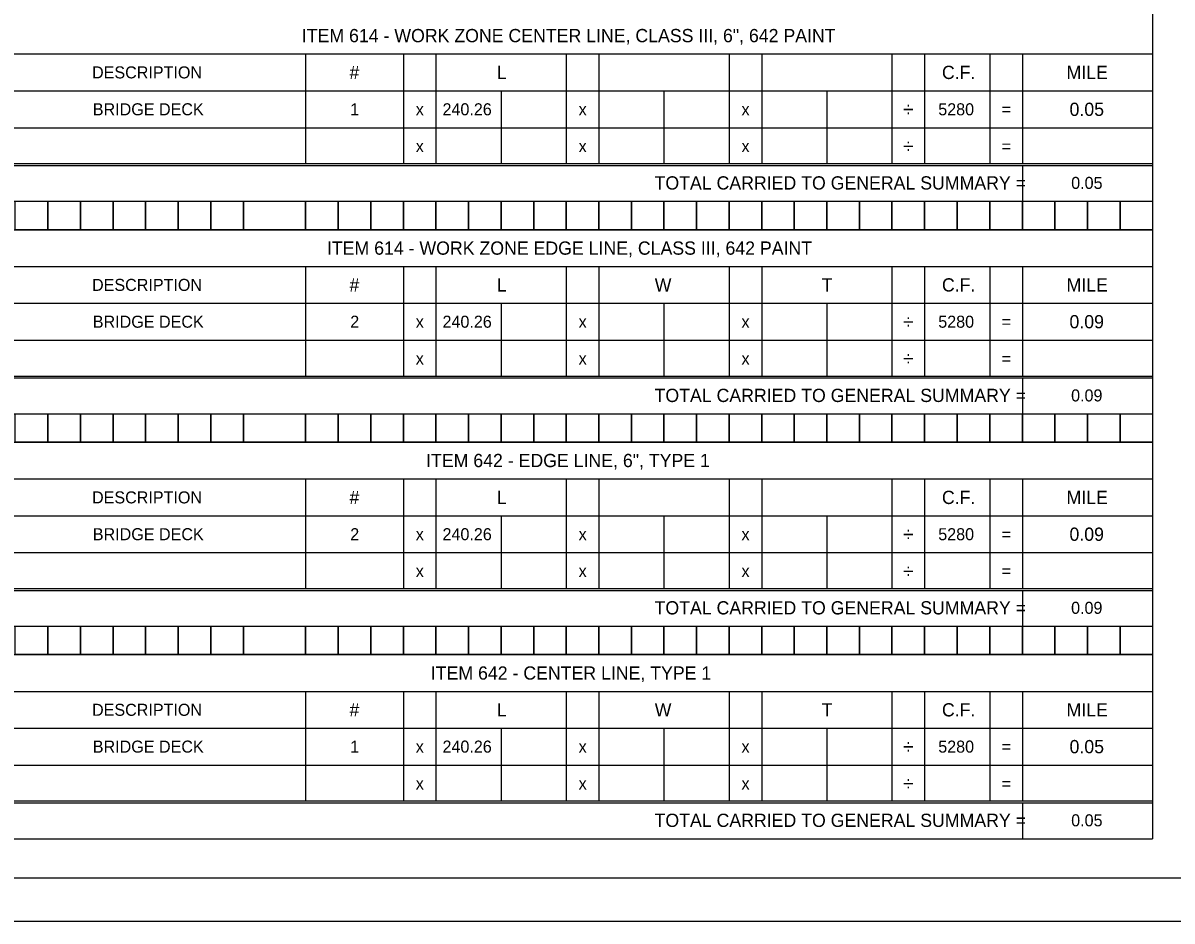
# Model space of a CAD drawing. Extents: x 0 to 34, y 0 to 22.
# Drawn here: x 11.43 to 24.79, y 0 to 10.44 of the extents above; entities that cross this region are included whole.
import ezdxf

# ---------------------------------------------------------------- set-up
doc = ezdxf.new("R2010")
doc.units = 0
for name, color, linetype in [('Default', 7, 'Continuous'), ('SH_Border', 7, 'Continuous'), ('SH_Cut_Line', 7, 'Continuous')]:
    doc.layers.add(name, color=color, linetype=linetype)

msp = doc.modelspace()

# ---------------------------------------------------------------- linework, layer by layer
at = {"layer": 'Default'}
for p, q in [((24.564, 11.279), (24.564, 8.786)), ((10.959, 10.082), (24.564, 10.082)), ((14.714, 10.082), (14.714, 8.808)), ((15.851, 10.082), (15.851, 8.808)), ((16.23, 10.082), (16.23, 8.808)), ((17.745, 10.082), (17.745, 8.808)), ((18.124, 10.082), (18.124, 8.808)), ((19.639, 10.082), (19.639, 8.808)), ((20.018, 10.082), (20.018, 8.808)), ((21.533, 10.082), (21.533, 8.808)), ((21.912, 10.082), (21.912, 8.808)), ((22.67, 10.082), (22.67, 8.808)), ((23.049, 10.082), (23.049, 8.808)), ((10.959, 9.654), (24.564, 9.654)), ((16.987, 9.654), (16.987, 8.808)), ((18.881, 9.654), (18.881, 8.808)), ((20.776, 9.654), (20.776, 8.808)), ((10.959, 9.225), (24.564, 9.225)), ((10.959, 8.808), (24.564, 8.808)), ((10.959, 8.786), (24.564, 8.786)), ((23.049, 8.786), (23.049, 8.369)), ((24.564, 8.808), (24.564, 6.315)), ((10.959, 8.369), (24.564, 8.369)), ((10.959, 8.039), (24.564, 8.039)), ((10.959, 7.611), (24.564, 7.611)), ((14.714, 7.611), (14.714, 6.337)), ((15.851, 7.611), (15.851, 6.337)), ((16.23, 7.611), (16.23, 6.337)), ((17.745, 7.611), (17.745, 6.337)), ((18.124, 7.611), (18.124, 6.337)), ((19.639, 7.611), (19.639, 6.337)), ((20.018, 7.611), (20.018, 6.337)), ((21.533, 7.611), (21.533, 6.337)), ((21.912, 7.611), (21.912, 6.337)), ((22.67, 7.611), (22.67, 6.337)), ((23.049, 7.611), (23.049, 6.337)), ((10.959, 7.183), (24.564, 7.183)), ((16.987, 7.183), (16.987, 6.337)), ((18.881, 7.183), (18.881, 6.337)), ((20.776, 7.183), (20.776, 6.337)), ((10.959, 6.755), (24.564, 6.755)), ((10.959, 6.337), (24.564, 6.337)), ((10.959, 6.315), (24.564, 6.315)), ((23.049, 6.315), (23.049, 5.898)), ((24.564, 6.337), (24.564, 3.845)), ((10.959, 5.898), (24.564, 5.898)), ((10.959, 5.569), (24.564, 5.569)), ((10.959, 5.141), (24.564, 5.141)), ((14.714, 5.141), (14.714, 3.867)), ((15.851, 5.141), (15.851, 3.867)), ((16.23, 5.141), (16.23, 3.867)), ((17.745, 5.141), (17.745, 3.867)), ((18.124, 5.141), (18.124, 3.867)), ((19.639, 5.141), (19.639, 3.867)), ((20.018, 5.141), (20.018, 3.867)), ((21.533, 5.141), (21.533, 3.867)), ((21.912, 5.141), (21.912, 3.867)), ((22.67, 5.141), (22.67, 3.867)), ((23.049, 5.141), (23.049, 3.867)), ((10.959, 4.712), (24.564, 4.712)), ((16.987, 4.712), (16.987, 3.867)), ((18.881, 4.712), (18.881, 3.867)), ((20.776, 4.712), (20.776, 3.867)), ((10.959, 4.284), (24.564, 4.284)), ((10.959, 3.867), (24.564, 3.867)), ((10.959, 3.845), (24.564, 3.845)), ((23.049, 3.845), (23.049, 3.428)), ((24.564, 3.867), (24.564, 1.374)), ((10.959, 3.428), (24.564, 3.428)), ((10.959, 3.098), (24.564, 3.098)), ((10.959, 2.67), (24.564, 2.67)), ((14.714, 2.67), (14.714, 1.396)), ((15.851, 2.67), (15.851, 1.396)), ((16.23, 2.67), (16.23, 1.396)), ((17.745, 2.67), (17.745, 1.396)), ((18.124, 2.67), (18.124, 1.396)), ((19.639, 2.67), (19.639, 1.396)), ((20.018, 2.67), (20.018, 1.396)), ((21.533, 2.67), (21.533, 1.396)), ((21.912, 2.67), (21.912, 1.396)), ((22.67, 2.67), (22.67, 1.396)), ((23.049, 2.67), (23.049, 1.396)), ((10.959, 2.242), (24.564, 2.242)), ((16.987, 2.242), (16.987, 1.396)), ((18.881, 2.242), (18.881, 1.396)), ((20.776, 2.242), (20.776, 1.396)), ((10.959, 1.814), (24.564, 1.814)), ((10.959, 1.396), (24.564, 1.396)), ((10.959, 1.374), (24.564, 1.374)), ((23.049, 1.374), (23.049, 0.957)), ((24.564, 1.396), (24.564, 0.957)), ((10.959, 0.957), (24.564, 0.957))]:
    msp.add_line(p, q, dxfattribs=at)
for points in [[(11.338, 8.369), (11.717, 8.369), (11.717, 8.039), (11.338, 8.039)], [(11.717, 8.369), (12.096, 8.369), (12.096, 8.039), (11.717, 8.039)], [(12.096, 8.369), (12.474, 8.369), (12.474, 8.039), (12.096, 8.039)], [(12.474, 8.369), (12.853, 8.369), (12.853, 8.039), (12.474, 8.039)], [(12.853, 8.369), (13.232, 8.369), (13.232, 8.039), (12.853, 8.039)], [(13.232, 8.369), (13.611, 8.369), (13.611, 8.039), (13.232, 8.039)], [(13.611, 8.369), (13.99, 8.369), (13.99, 8.039), (13.611, 8.039)], [(13.99, 8.369), (14.714, 8.369), (14.714, 8.039), (13.99, 8.039)], [(14.714, 8.369), (15.093, 8.369), (15.093, 8.039), (14.714, 8.039)], [(15.093, 8.369), (15.472, 8.369), (15.472, 8.039), (15.093, 8.039)], [(15.472, 8.369), (15.851, 8.369), (15.851, 8.039), (15.472, 8.039)], [(15.851, 8.369), (16.23, 8.369), (16.23, 8.039), (15.851, 8.039)], [(16.23, 8.369), (16.609, 8.369), (16.609, 8.039), (16.23, 8.039)], [(16.609, 8.369), (16.987, 8.369), (16.987, 8.039), (16.609, 8.039)], [(16.987, 8.369), (17.366, 8.369), (17.366, 8.039), (16.987, 8.039)], [(17.366, 8.369), (17.745, 8.369), (17.745, 8.039), (17.366, 8.039)], [(17.745, 8.369), (18.124, 8.369), (18.124, 8.039), (17.745, 8.039)], [(18.124, 8.369), (18.503, 8.369), (18.503, 8.039), (18.124, 8.039)], [(18.503, 8.369), (18.881, 8.369), (18.881, 8.039), (18.503, 8.039)], [(18.881, 8.369), (19.26, 8.369), (19.26, 8.039), (18.881, 8.039)], [(19.26, 8.369), (19.639, 8.369), (19.639, 8.039), (19.26, 8.039)], [(19.639, 8.369), (20.018, 8.369), (20.018, 8.039), (19.639, 8.039)], [(20.018, 8.369), (20.397, 8.369), (20.397, 8.039), (20.018, 8.039)], [(20.397, 8.369), (20.776, 8.369), (20.776, 8.039), (20.397, 8.039)], [(20.776, 8.369), (21.154, 8.369), (21.154, 8.039), (20.776, 8.039)], [(21.154, 8.369), (21.533, 8.369), (21.533, 8.039), (21.154, 8.039)], [(21.533, 8.369), (21.912, 8.369), (21.912, 8.039), (21.533, 8.039)], [(21.912, 8.369), (22.291, 8.369), (22.291, 8.039), (21.912, 8.039)], [(22.291, 8.369), (22.67, 8.369), (22.67, 8.039), (22.291, 8.039)], [(22.67, 8.369), (23.049, 8.369), (23.049, 8.039), (22.67, 8.039)], [(23.049, 8.369), (23.427, 8.369), (23.427, 8.039), (23.049, 8.039)], [(23.427, 8.369), (23.806, 8.369), (23.806, 8.039), (23.427, 8.039)], [(23.806, 8.369), (24.185, 8.369), (24.185, 8.039), (23.806, 8.039)], [(24.185, 8.369), (24.564, 8.369), (24.564, 8.039), (24.185, 8.039)], [(11.338, 5.898), (11.717, 5.898), (11.717, 5.569), (11.338, 5.569)], [(11.717, 5.898), (12.096, 5.898), (12.096, 5.569), (11.717, 5.569)], [(12.096, 5.898), (12.474, 5.898), (12.474, 5.569), (12.096, 5.569)], [(12.474, 5.898), (12.853, 5.898), (12.853, 5.569), (12.474, 5.569)], [(12.853, 5.898), (13.232, 5.898), (13.232, 5.569), (12.853, 5.569)], [(13.232, 5.898), (13.611, 5.898), (13.611, 5.569), (13.232, 5.569)], [(13.611, 5.898), (13.99, 5.898), (13.99, 5.569), (13.611, 5.569)], [(13.99, 5.898), (14.714, 5.898), (14.714, 5.569), (13.99, 5.569)], [(14.714, 5.898), (15.093, 5.898), (15.093, 5.569), (14.714, 5.569)], [(15.093, 5.898), (15.472, 5.898), (15.472, 5.569), (15.093, 5.569)], [(15.472, 5.898), (15.851, 5.898), (15.851, 5.569), (15.472, 5.569)], [(15.851, 5.898), (16.23, 5.898), (16.23, 5.569), (15.851, 5.569)], [(16.23, 5.898), (16.609, 5.898), (16.609, 5.569), (16.23, 5.569)], [(16.609, 5.898), (16.987, 5.898), (16.987, 5.569), (16.609, 5.569)], [(16.987, 5.898), (17.366, 5.898), (17.366, 5.569), (16.987, 5.569)], [(17.366, 5.898), (17.745, 5.898), (17.745, 5.569), (17.366, 5.569)], [(17.745, 5.898), (18.124, 5.898), (18.124, 5.569), (17.745, 5.569)], [(18.124, 5.898), (18.503, 5.898), (18.503, 5.569), (18.124, 5.569)], [(18.503, 5.898), (18.881, 5.898), (18.881, 5.569), (18.503, 5.569)], [(18.881, 5.898), (19.26, 5.898), (19.26, 5.569), (18.881, 5.569)], [(19.26, 5.898), (19.639, 5.898), (19.639, 5.569), (19.26, 5.569)], [(19.639, 5.898), (20.018, 5.898), (20.018, 5.569), (19.639, 5.569)], [(20.018, 5.898), (20.397, 5.898), (20.397, 5.569), (20.018, 5.569)], [(20.397, 5.898), (20.776, 5.898), (20.776, 5.569), (20.397, 5.569)], [(20.776, 5.898), (21.154, 5.898), (21.154, 5.569), (20.776, 5.569)], [(21.154, 5.898), (21.533, 5.898), (21.533, 5.569), (21.154, 5.569)], [(21.533, 5.898), (21.912, 5.898), (21.912, 5.569), (21.533, 5.569)], [(21.912, 5.898), (22.291, 5.898), (22.291, 5.569), (21.912, 5.569)], [(22.291, 5.898), (22.67, 5.898), (22.67, 5.569), (22.291, 5.569)], [(22.67, 5.898), (23.049, 5.898), (23.049, 5.569), (22.67, 5.569)], [(23.049, 5.898), (23.427, 5.898), (23.427, 5.569), (23.049, 5.569)], [(23.427, 5.898), (23.806, 5.898), (23.806, 5.569), (23.427, 5.569)], [(23.806, 5.898), (24.185, 5.898), (24.185, 5.569), (23.806, 5.569)], [(24.185, 5.898), (24.564, 5.898), (24.564, 5.569), (24.185, 5.569)], [(11.338, 3.428), (11.717, 3.428), (11.717, 3.098), (11.338, 3.098)], [(11.717, 3.428), (12.096, 3.428), (12.096, 3.098), (11.717, 3.098)], [(12.096, 3.428), (12.474, 3.428), (12.474, 3.098), (12.096, 3.098)], [(12.474, 3.428), (12.853, 3.428), (12.853, 3.098), (12.474, 3.098)], [(12.853, 3.428), (13.232, 3.428), (13.232, 3.098), (12.853, 3.098)], [(13.232, 3.428), (13.611, 3.428), (13.611, 3.098), (13.232, 3.098)], [(13.611, 3.428), (13.99, 3.428), (13.99, 3.098), (13.611, 3.098)], [(13.99, 3.428), (14.714, 3.428), (14.714, 3.098), (13.99, 3.098)], [(14.714, 3.428), (15.093, 3.428), (15.093, 3.098), (14.714, 3.098)], [(15.093, 3.428), (15.472, 3.428), (15.472, 3.098), (15.093, 3.098)], [(15.472, 3.428), (15.851, 3.428), (15.851, 3.098), (15.472, 3.098)], [(15.851, 3.428), (16.23, 3.428), (16.23, 3.098), (15.851, 3.098)], [(16.23, 3.428), (16.609, 3.428), (16.609, 3.098), (16.23, 3.098)], [(16.609, 3.428), (16.987, 3.428), (16.987, 3.098), (16.609, 3.098)], [(16.987, 3.428), (17.366, 3.428), (17.366, 3.098), (16.987, 3.098)], [(17.366, 3.428), (17.745, 3.428), (17.745, 3.098), (17.366, 3.098)], [(17.745, 3.428), (18.124, 3.428), (18.124, 3.098), (17.745, 3.098)], [(18.124, 3.428), (18.503, 3.428), (18.503, 3.098), (18.124, 3.098)], [(18.503, 3.428), (18.881, 3.428), (18.881, 3.098), (18.503, 3.098)], [(18.881, 3.428), (19.26, 3.428), (19.26, 3.098), (18.881, 3.098)], [(19.26, 3.428), (19.639, 3.428), (19.639, 3.098), (19.26, 3.098)], [(19.639, 3.428), (20.018, 3.428), (20.018, 3.098), (19.639, 3.098)], [(20.018, 3.428), (20.397, 3.428), (20.397, 3.098), (20.018, 3.098)], [(20.397, 3.428), (20.776, 3.428), (20.776, 3.098), (20.397, 3.098)], [(20.776, 3.428), (21.154, 3.428), (21.154, 3.098), (20.776, 3.098)], [(21.154, 3.428), (21.533, 3.428), (21.533, 3.098), (21.154, 3.098)], [(21.533, 3.428), (21.912, 3.428), (21.912, 3.098), (21.533, 3.098)], [(21.912, 3.428), (22.291, 3.428), (22.291, 3.098), (21.912, 3.098)], [(22.291, 3.428), (22.67, 3.428), (22.67, 3.098), (22.291, 3.098)], [(22.67, 3.428), (23.049, 3.428), (23.049, 3.098), (22.67, 3.098)], [(23.049, 3.428), (23.427, 3.428), (23.427, 3.098), (23.049, 3.098)], [(23.427, 3.428), (23.806, 3.428), (23.806, 3.098), (23.427, 3.098)], [(23.806, 3.428), (24.185, 3.428), (24.185, 3.098), (23.806, 3.098)], [(24.185, 3.428), (24.564, 3.428), (24.564, 3.098), (24.185, 3.098)]]:
    msp.add_lwpolyline(points, close=True, dxfattribs=at)
at = {"layer": 'SH_Border'}
msp.add_lwpolyline([(1.5, 21.5), (33.5, 21.5), (33.5, 0.5), (1.5, 0.5)], close=True, dxfattribs=at)
at = {"layer": 'SH_Cut_Line'}
msp.add_lwpolyline([(0, 0), (34, 0), (34, 22), (0, 22)], close=True, dxfattribs=at)

# ---------------------------------------------------------------- texts
at = {"layer": 'Default'}
for s, height, p in [('ITEM 614 - WORK ZONE CENTER LINE, CLASS III, 6", 642 PAINT', 0.154, (14.67, 10.219)), ('DESCRIPTION', 0.14, (12.23, 9.798)), ('#', 0.154, (15.224, 9.791)), ('L', 0.154, (16.937, 9.791)), ('C.F.', 0.154, (22.114, 9.791)), ('MILE', 0.154, (23.563, 9.791)), ('BRIDGE DECK', 0.14, (12.239, 9.369)), ('1', 0.14, (15.233, 9.369)), ('240.26', 0.14, (16.306, 9.369)), ('÷', 0.168, (21.661, 9.355)), ('5280', 0.14, (22.071, 9.369)), ('0.05', 0.154, (23.598, 9.362)), ('x', 0.14, (15.995, 9.369)), ('x', 0.14, (17.889, 9.369)), ('x', 0.14, (19.783, 9.369)), ('=', 0.14, (22.809, 9.369)), ('x', 0.14, (15.995, 8.941)), ('x', 0.14, (17.889, 8.941)), ('x', 0.14, (19.783, 8.941)), ('÷', 0.168, (21.661, 8.927)), ('=', 0.14, (22.809, 8.941)), ('TOTAL CARRIED TO GENERAL SUMMARY =', 0.154, (18.772, 8.506)), ('0.05', 0.14, (23.617, 8.513)), ('ITEM 614 - WORK ZONE EDGE LINE, CLASS III, 642 PAINT', 0.154, (14.962, 7.748)), ('DESCRIPTION', 0.14, (12.23, 7.327)), ('#', 0.154, (15.224, 7.32)), ('L', 0.154, (16.937, 7.32)), ('W', 0.154, (18.774, 7.32)), ('T', 0.154, (20.716, 7.32)), ('C.F.', 0.154, (22.114, 7.32)), ('MILE', 0.154, (23.563, 7.32)), ('BRIDGE DECK', 0.14, (12.239, 6.899)), ('2', 0.14, (15.233, 6.899)), ('x', 0.14, (15.995, 6.899)), ('240.26', 0.14, (16.306, 6.899)), ('x', 0.14, (17.889, 6.899)), ('x', 0.14, (19.783, 6.899)), ('÷', 0.168, (21.661, 6.885)), ('5280', 0.14, (22.071, 6.899)), ('=', 0.14, (22.809, 6.899)), ('0.09', 0.154, (23.597, 6.892)), ('x', 0.14, (15.995, 6.471)), ('x', 0.14, (17.889, 6.471)), ('x', 0.14, (19.783, 6.471)), ('÷', 0.168, (21.661, 6.457)), ('=', 0.14, (22.809, 6.471)), ('TOTAL CARRIED TO GENERAL SUMMARY =', 0.154, (18.772, 6.035)), ('0.09', 0.14, (23.616, 6.042)), ('ITEM 642 - EDGE LINE, 6", TYPE 1', 0.154, (16.115, 5.278)), ('DESCRIPTION', 0.14, (12.23, 4.856)), ('#', 0.154, (15.224, 4.849)), ('L', 0.154, (16.937, 4.849)), ('C.F.', 0.154, (22.114, 4.849)), ('MILE', 0.154, (23.563, 4.849)), ('BRIDGE DECK', 0.14, (12.239, 4.428)), ('2', 0.14, (15.233, 4.428)), ('240.26', 0.14, (16.306, 4.428)), ('÷', 0.168, (21.661, 4.414)), ('5280', 0.14, (22.071, 4.428)), ('0.09', 0.154, (23.597, 4.421)), ('x', 0.14, (15.995, 4.428)), ('x', 0.14, (17.889, 4.428)), ('x', 0.14, (19.783, 4.428)), ('=', 0.14, (22.809, 4.428)), ('x', 0.14, (15.995, 4)), ('x', 0.14, (17.889, 4)), ('x', 0.14, (19.783, 4)), ('÷', 0.168, (21.661, 3.986)), ('=', 0.14, (22.809, 4)), ('TOTAL CARRIED TO GENERAL SUMMARY =', 0.154, (18.772, 3.565)), ('0.09', 0.14, (23.616, 3.572)), ('ITEM 642 - CENTER LINE, TYPE 1', 0.154, (16.17, 2.807)), ('DESCRIPTION', 0.14, (12.23, 2.386)), ('#', 0.154, (15.224, 2.379)), ('L', 0.154, (16.937, 2.379)), ('W', 0.154, (18.774, 2.379)), ('T', 0.154, (20.716, 2.379)), ('C.F.', 0.154, (22.114, 2.379)), ('MILE', 0.154, (23.563, 2.379)), ('BRIDGE DECK', 0.14, (12.239, 1.958)), ('1', 0.14, (15.233, 1.958)), ('x', 0.14, (15.995, 1.958)), ('240.26', 0.14, (16.306, 1.958)), ('x', 0.14, (17.889, 1.958)), ('x', 0.14, (19.783, 1.958)), ('÷', 0.168, (21.661, 1.944)), ('5280', 0.14, (22.071, 1.958)), ('=', 0.14, (22.809, 1.958)), ('0.05', 0.154, (23.598, 1.951)), ('x', 0.14, (15.995, 1.529)), ('x', 0.14, (17.889, 1.529)), ('x', 0.14, (19.783, 1.529)), ('÷', 0.168, (21.661, 1.515)), ('=', 0.14, (22.809, 1.529)), ('TOTAL CARRIED TO GENERAL SUMMARY =', 0.154, (18.772, 1.094)), ('0.05', 0.14, (23.617, 1.101))]:
    msp.add_text(s, height=height, dxfattribs=at).set_placement(p)

doc.saveas('drawing.dxf')
